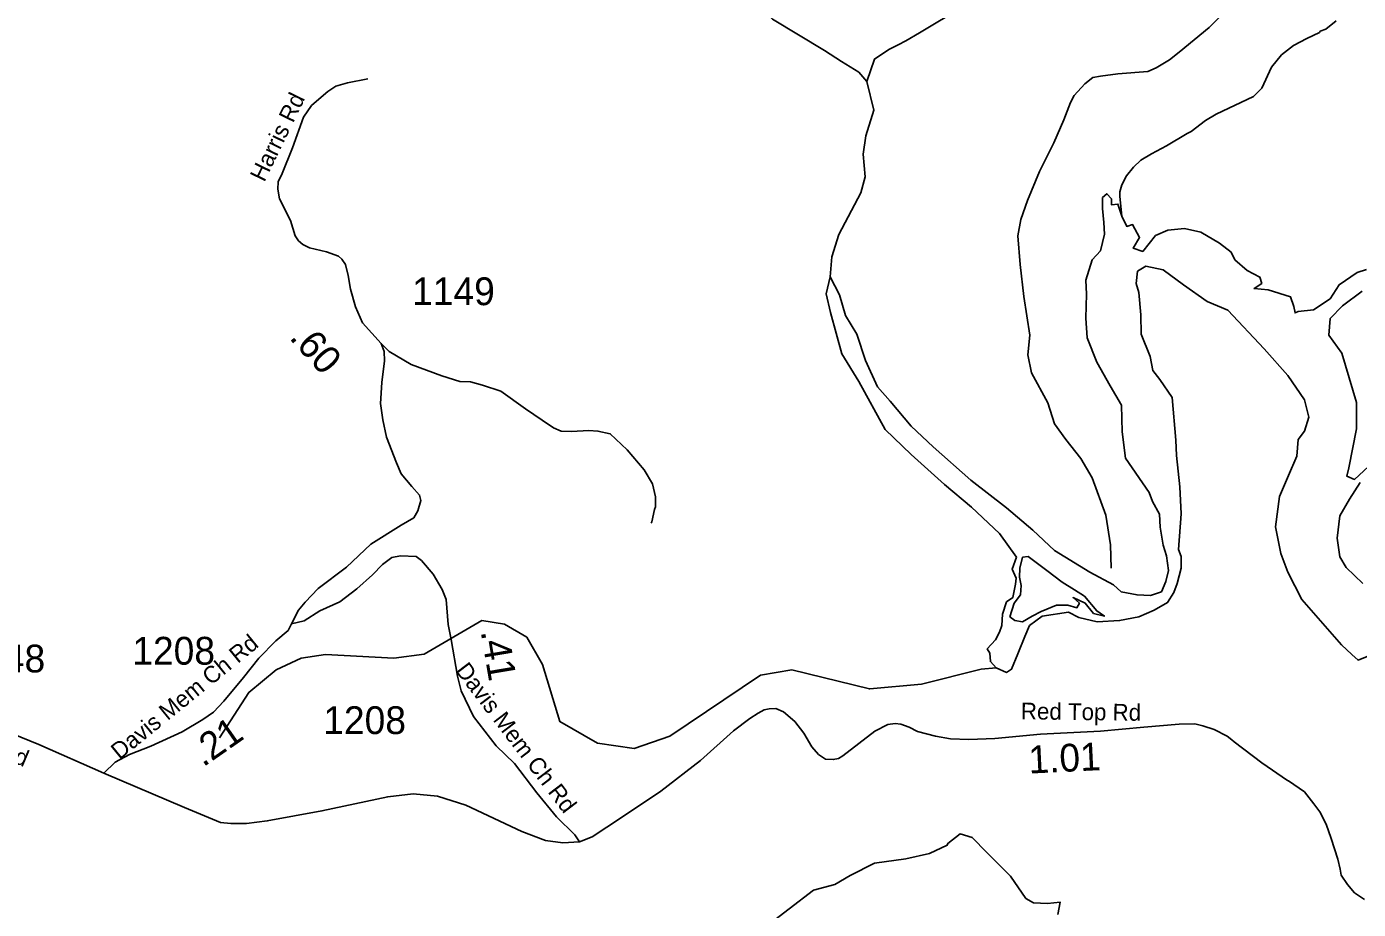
# Model space of a CAD drawing. Extents: x 1248224 to 1454986, y 825081 to 985870.
# Drawn here: x 1318874 to 1324862, y 870778 to 874747 of the extents above; entities that cross this region are included whole.
import ezdxf

# ---------------------------------------------------------------- set-up
doc = ezdxf.new("R2010")
doc.units = 0
for name, color, linetype in [('Exist Hydrographic Creek Single Shore', 7, 'Continuous'), ('Exist Hydrographic Island Shore', 7, 'Continuous'), ('Exist Hydrographic Misc Water Feature', 7, 'Continuous'), ('Exist Hydrographic Reservoir', 7, 'Continuous'), ('Exist Road Non-System Type 51', 7, 'Continuous'), ('Exist Road Secondary Mileage Hundredths English Label', 7, 'Continuous'), ('Exist Road Secondary Type 41 Attributed', 7, 'Continuous'), ('Exist Road Secondary Type 51 Attributed', 7, 'Continuous'), ('Exist Road Secondary Type 51 Label', 7, 'Continuous'), ('Exist Road Secondary Type 51 Number Label', 7, 'Continuous')]:
    doc.layers.add(name, color=color, linetype=linetype)

msp = doc.modelspace()

# ---------------------------------------------------------------- linework, layer by layer
at = {"layer": 'Exist Hydrographic Creek Single Shore'}
for points in [[(1320808.8, 876973.4), (1320929.1, 876789.6), (1321094.1, 876465.3), (1321322.1, 875990), (1321499.4, 875654.2), (1321600.7, 875464), (1321790.5, 875203.3), (1321980.7, 875014.1), (1322227.6, 874779.7), (1322461.9, 874640.2), (1322537.9, 874589.5), (1322616.2, 874542.5), (1322652.8, 874500.3), (1322683.7, 874370.7), (1322647.2, 874255.2), (1322635.9, 874173.6), (1322644.3, 874072.2), (1322624.6, 873998.9), (1322526.1, 873813), (1322495.2, 873711.7), (1322486.8, 873622.7)], [(1319741.5, 871549.2), (1319872.9, 871753.6), (1319996.9, 871855.9), (1320109.3, 871907), (1320217.3, 871924.5), (1320525.3, 871908.4), (1320661.1, 871926), (1320920.9, 872076.4)], [(1322666.1, 871769.6), (1322663.5, 871769.4), (1322315.6, 871855.1), (1322173.6, 871831.7), (1321766.5, 871557.6), (1321606.6, 871501.7), (1321440.6, 871524.8), (1321271.9, 871622.9), (1321193.1, 871878.5), (1321123, 872002.6), (1321022.3, 872061.1), (1320920.9, 872076.4)]]:
    msp.add_lwpolyline(points, dxfattribs=at)
at = {"layer": 'Exist Hydrographic Island Shore'}
msp.add_lwpolyline([(1323294.9, 872094), (1323315, 872154.5), (1323343.7, 872191.9), (1323346.6, 872235.1), (1323338, 872272.5), (1323340.9, 872312.8), (1323352.4, 872361.7), (1323378.3, 872364.6), (1323461.7, 872301.3), (1323530.7, 872249.4), (1323585.3, 872214.9), (1323631.4, 872186.1), (1323686, 872119.9), (1323720.5, 872096.9), (1323671.6, 872108.4), (1323634.2, 872154.5), (1323579.6, 872180.4), (1323608.4, 872154.5), (1323596.9, 872134.3), (1323556.6, 872145.8), (1323504.8, 872145.8), (1323435.8, 872117), (1323395.5, 872096.9), (1323352.4, 872071), (1323317.9, 872076.7), (1323294.9, 872094)], dxfattribs=at)
at = {"layer": 'Exist Hydrographic Misc Water Feature'}
for points in [[(1323036.2, 875103.7), (1323044.7, 875085.8), (1323047.5, 875045.7), (1323065.3, 874965.2), (1323091.7, 874908.5), (1323098.8, 874876.3), (1323087.6, 874836.6), (1322889.1, 874719.1), (1322828.1, 874682.7), (1322793.5, 874665.7), (1322750.7, 874644.6), (1322686.4, 874600.8), (1322652.8, 874500.3)], [(1324762.5, 874772.2), (1324715.5, 874735.5), (1324691.2, 874726.3), (1324687, 874720.4), (1324630.2, 874694), (1324571.4, 874661.7), (1324516.1, 874619.4), (1324472.5, 874564.6), (1324427.8, 874470), (1324390.8, 874433.1), (1324222.6, 874353.9), (1324175.7, 874325.3), (1324110.3, 874275.2), (1324092.4, 874267), (1324000.4, 874210.4)], [(1324000.4, 874210.4), (1323933, 874175), (1323884.6, 874145.8), (1323851.6, 874114.7), (1323820.6, 874075.7), (1323799.5, 874036.3), (1323790.5, 874004.5), (1323789.9, 873982.6), (1323799.6, 873894.2)], [(1323233.8, 871863.8), (1323166.6, 871857.8), (1322897.6, 871790.9), (1322666.1, 871769.6)]]:
    msp.add_lwpolyline(points, dxfattribs=at)
at = {"layer": 'Exist Hydrographic Reservoir'}
for points in [[(1323921.9, 872652.4), (1323815.4, 872806.5), (1323801, 872924.5), (1323798.1, 873045.4), (1323746.4, 873131.8), (1323686, 873238.3), (1323642.8, 873347.6), (1323637.1, 873436.9), (1323639.9, 873543.4), (1323637.1, 873606.7), (1323665.8, 873698.8), (1323703.2, 873739.1), (1323720.5, 873813.9), (1323717.6, 873865.7), (1323711.8, 873929), (1323711.8, 873978), (1323732, 873995.2), (1323752.1, 873972.2), (1323752.1, 873946.3), (1323780.9, 873949.2), (1323799.6, 873894.2), (1323821.1, 873848.5), (1323847, 873857.1), (1323878.7, 873799.5), (1323849.9, 873750.6), (1323893.1, 873736.2), (1323950.6, 873808.2), (1324005.2, 873831.2), (1324080, 873839.8), (1324154.8, 873822.5), (1324238.2, 873773.6), (1324290, 873733.3), (1324307.2, 873698.8), (1324361.9, 873649.9), (1324419.4, 873621.1), (1324428, 873592.3), (1324393.5, 873569.3), (1324456.8, 873563.5), (1324557.5, 873531.8), (1324571.8, 873488.7), (1324577.6, 873459.9), (1324592, 873465.6), (1324661, 873474.3), (1324735.8, 873523.2), (1324776, 873586.5), (1324856.6, 873641.2), (1324899.7, 873655.6)], [(1324059.2, 872677.2), (1324044.7, 872818.1), (1324041.9, 872887.2), (1324024.6, 873080), (1323970, 873160.6), (1323938.3, 873200.9), (1323926.8, 873264.2), (1323886.5, 873365), (1323883.7, 873451.3), (1323875, 873552.1), (1323863.5, 873592.4), (1323869.3, 873647), (1323906.7, 873670.1), (1323984.3, 873652.8), (1324076.4, 873586.6), (1324182.8, 873511.8), (1324274.8, 873471.5), (1324438.8, 873298.8), (1324545.2, 873177.9), (1324620, 873068.5), (1324640.1, 872990.8), (1324620, 872927.5), (1324591.2, 872890), (1324585.5, 872815.2), (1324548.1, 872728.9), (1324507.8, 872633.9), (1324490.5, 872498.6), (1324513.6, 872377.7), (1324545.2, 872294.2), (1324608.2, 872172), (1324786.5, 871967.6), (1324832.5, 871924.4), (1324861.3, 871898.5), (1324924.5, 871924.4)], [(1322486.8, 873622.7), (1322469.7, 873545.6), (1322489.4, 873461.1), (1322540, 873275.3), (1322616, 873151.3), (1322734.1, 872935.9), (1322852.3, 872823.3), (1323001.5, 872688.1), (1323122.5, 872586.7), (1323249.1, 872468.4), (1323325.1, 872361.4)], [(1323654.4, 872293.8), (1323496.8, 872392.4), (1323398.3, 872482.5), (1323280.1, 872583.9), (1323119.7, 872707.8), (1322950.8, 872857.1), (1322852.3, 872950), (1322756.6, 873062.7), (1322700.3, 873127.4), (1322646.9, 873245.7), (1322607.5, 873364), (1322556.8, 873448.5), (1322528.7, 873541.5), (1322486.8, 873622.7)], [(1324879.6, 873557.7), (1324790.4, 873491.5), (1324735.8, 873434), (1324730, 873359.1), (1324787.6, 873278.6), (1324853.7, 873056.9), (1324853.7, 872938.9), (1324819.2, 872763.3), (1324810.6, 872725.9), (1324845.1, 872711.5), (1324908.4, 872769.1)], [(1324871, 872697.1), (1324822.1, 872622.3), (1324778.9, 872547.5), (1324767.4, 872446.7), (1324778.9, 872363.3), (1324807.6, 872315.5), (1324882.4, 872243.5)], [(1323325.1, 872361.4), (1323305.7, 872307.1), (1323323, 872266.8), (1323320.1, 872240.9), (1323308.6, 872180.4), (1323279.9, 872160.3), (1323262.6, 872105.6), (1323259.7, 872053.8), (1323248.2, 872025), (1323231, 871990.5), (1323193.6, 871950.2), (1323205.1, 871930), (1323207.9, 871892.6), (1323233.8, 871863.8), (1323279.9, 871843.7), (1323302.9, 871858.1), (1323331.6, 871927.1), (1323363.3, 872004.8), (1323383.4, 872053.8), (1323440.9, 872096.9), (1323558.8, 872114.2), (1323604.9, 872091.2), (1323688.3, 872071), (1323788.9, 872076.8), (1323875.2, 872094.1), (1323944.3, 872122.9), (1324004.7, 872157.4), (1324033.4, 872203.4), (1324047.8, 872243.7), (1324065.1, 872312.8), (1324065.1, 872364.6), (1324053.6, 872396.3), (1324065, 872556.3), (1324059.2, 872677.2)], [(1323654.4, 872293.8), (1323760.8, 872237.9), (1323795.3, 872206.3), (1323867.2, 872191.9), (1323927.6, 872189), (1323976.5, 872206.3), (1323996.6, 872252.3), (1324008.2, 872301.3), (1323999.5, 872367.5), (1323985.1, 872416.4), (1323970.8, 872497), (1323967.9, 872554.5), (1323936.2, 872612.1), (1323921.9, 872652.4)], [(1323366.8, 870827.7), (1323298.6, 870928.2), (1323192.2, 871034.7), (1323126, 871100.9), (1323071.4, 871118.2), (1323016.7, 871075), (1323013.8, 871066.4), (1322933.3, 871029), (1322826.9, 871005.9), (1322686, 870985.8), (1322576.7, 870931.1), (1322507.6, 870890.8), (1322412.7, 870864.9), (1322303.4, 870781.4), (1322153.9, 870666.3)], [(1323510.6, 870755.7), (1323522.2, 870810.4), (1323464.6, 870804.6), (1323401.3, 870807.5), (1323366.8, 870827.7)]]:
    msp.add_lwpolyline(points, dxfattribs=at)
at = {"layer": 'Exist Road Non-System Type 51'}
for points in [[(1324013.5, 874596.9), (1323953.5, 874561.8), (1323915.8, 874545.6), (1323781, 874534.8), (1323702.9, 874524), (1323667.9, 874518.6), (1323632.8, 874489), (1323584.3, 874437.7), (1323568.1, 874405.4), (1323538.5, 874327.2), (1323492.7, 874224.7), (1323428, 874095.2), (1323374.1, 873965.8), (1323344.5, 873879.5), (1323331, 873806.7), (1323341.8, 873677.2), (1323357.9, 873534.3), (1323384.9, 873360.3), (1323376.9, 873271.3), (1323393, 873190.4), (1323465.8, 873055.6), (1323495.4, 872961.2), (1323546.6, 872891.1), (1323614, 872804.8), (1323665.2, 872718.5), (1323727, 872549.9), (1323748.5, 872417.8), (1323751.2, 872312.6)], [(1320468.2, 873322.3), (1320503.6, 873285.7), (1320603.1, 873227.4), (1320741.4, 873176.4), (1320821.5, 873152.1), (1320870.1, 873149.7), (1320923.5, 873135.1), (1321006, 873108.4), (1321117.6, 873028.3), (1321192.9, 872977.2), (1321243.8, 872943.2), (1321277.8, 872928.7), (1321323.9, 872926.2), (1321401.6, 872931.1), (1321442.8, 872928.7), (1321498.7, 872916.5), (1321573.9, 872843.7), (1321651.6, 872753.8), (1321688, 872690.7), (1321702.5, 872632.4), (1321702.5, 872588.6), (1321697.7, 872576.5), (1321685.5, 872520.6), (1321682.7, 872514.3)]]:
    msp.add_lwpolyline(points, dxfattribs=at)
at = {"layer": 'Exist Road Secondary Type 41 Attributed'}
for points in [[(1320065.3, 872061.3), (1320096.8, 872124.2), (1320126.4, 872159.3), (1320185.5, 872220.4), (1320313.1, 872316.7), (1320422.3, 872420.6), (1320557.7, 872505.9), (1320614.7, 872538.9), (1320632.8, 872569.7), (1320646.8, 872617.2), (1320641.2, 872641), (1320606.3, 872678.7), (1320558.8, 872736), (1320537.8, 872786.4), (1320491.7, 872901), (1320475.2, 872979.8), (1320465.4, 873052.5), (1320471, 873147.6), (1320483.6, 873244.1), (1320482.2, 873286), (1320468.2, 873322.3), (1320426.4, 873368.8), (1320384.5, 873414.9), (1320352.3, 873487.6), (1320330, 873567.3), (1320320.2, 873627.4), (1320307.6, 873677.8), (1320290.9, 873701.5), (1320276.9, 873715.5), (1320222.4, 873733.7), (1320145.6, 873751.9), (1320116.3, 873767.2), (1320096.7, 873784), (1320081.4, 873806.4), (1320060.4, 873874.9), (1320010.4, 873973.3), (1320003.4, 874016.7), (1320004.8, 874048.8), (1320023, 874086.6), (1320069.1, 874201.2), (1320119.4, 874339.6), (1320155.6, 874392), (1320187.7, 874421.3), (1320228.3, 874454.9), (1320264.6, 874478.7), (1320316.3, 874494), (1320408.1, 874512.1)], [(1320065.3, 872061.3), (1320121.4, 872076.1), (1320191.9, 872120.2), (1320283.1, 872161.4), (1320359.5, 872218.8), (1320428.6, 872282.1), (1320474.2, 872329.1), (1320516.8, 872360), (1320555.1, 872367.4), (1320625.6, 872364.5), (1320649.2, 872346.8), (1320702.1, 872285), (1320743.2, 872215.9), (1320760.9, 872171.7), (1320769.7, 872058.4), (1320782.9, 871992.2)], [(1320782.9, 871992.2), (1320810.9, 871827.4), (1320828.5, 871761.2), (1320884.2, 871645.9), (1320985.7, 871513.4), (1321068, 871434), (1321168, 871301.6), (1321257.3, 871194.8), (1321339.6, 871113.9), (1321360.2, 871081.5)]]:
    msp.add_lwpolyline(points, dxfattribs=at)
at = {"layer": 'Exist Road Secondary Type 51 Attributed'}
for points in [[(1324243.7, 874795.2), (1324191.1, 874742.5), (1324056.1, 874632), (1324013.5, 874596.9)], [(1319221.9, 871390), (1319272.6, 871440), (1319337.3, 871475.3), (1319432.8, 871512.1), (1319574, 871576.8), (1319666.6, 871631.3), (1319715.1, 871665.1), (1319760.7, 871715.1), (1319848.9, 871821.1), (1319918, 871907.9), (1319994.4, 871985.8), (1320049.9, 872032.3), (1320065.3, 872061.3)], [(1318052.7, 871939.5), (1318326.1, 871792.7), (1318611.3, 871648.5), (1318928.9, 871519), (1319221.9, 871390)], [(1321360.2, 871081.5), (1321417.8, 871104), (1321549.3, 871191.1), (1321725.5, 871309.4), (1321903.9, 871447.8), (1322053.4, 871581.7), (1322125.4, 871635.7), (1322163.3, 871660.3), (1322191.2, 871674.8), (1322213.5, 871680.4), (1322243.6, 871681.5), (1322278.2, 871665.9), (1322328.3, 871622.4), (1322368.5, 871569.9), (1322405.3, 871508.5), (1322435.4, 871475), (1322466.6, 871453.8), (1322501.2, 871451.6), (1322524.6, 871456.1), (1322543.6, 871468.3), (1322688.5, 871578.8), (1322746.1, 871610.1), (1322779.5, 871614.6), (1322805.2, 871611.2), (1322842, 871597.8), (1322879.9, 871577.7), (1322961.3, 871557.6), (1323028.2, 871545.4), (1323110.4, 871542.2), (1323227.5, 871546.7), (1323433.7, 871565.7), (1323702.8, 871578.8), (1323897.9, 871597.8), (1324056.3, 871611.2), (1324126.5, 871612.3), (1324163.3, 871603.4), (1324213.5, 871586.6), (1324272.6, 871557.6), (1324293.3, 871540.6), (1324303.5, 871532.2), (1324428.4, 871437.4), (1324544.3, 871358.1), (1324547.7, 871355.9), (1324620.2, 871306.8), (1324662.5, 871253.2), (1324689.3, 871217.5), (1324718.3, 871161.7), (1324740.6, 871097), (1324769.5, 871004.2), (1324780.7, 870959.5), (1324785.1, 870932.8), (1324814.1, 870890.3), (1324845.4, 870852.4), (1324890, 870823.4)], [(1319221.9, 871390), (1319584.6, 871236.3), (1319745.2, 871168.5), (1319791.7, 871164.7), (1319863.2, 871164.7), (1319956.1, 871176.3), (1320201.9, 871220.8), (1320497.9, 871284.7), (1320612.1, 871298.3), (1320722.3, 871286.7), (1320849.2, 871246.2), (1321100.7, 871128), (1321207.2, 871087.4), (1321284.6, 871077.7), (1321360.2, 871081.5)]]:
    msp.add_lwpolyline(points, dxfattribs=at)

# ---------------------------------------------------------------- texts
at = {"layer": 'Exist Road Secondary Mileage Hundredths English Label'}
for s, rotation, p in [('.60', 312.00363, (1320051.7, 873346.3)), ('.41', 279.62064, (1320915.4, 872027.9)), ('.21', 34.8966, (1319667.8, 871415.8)), ('1.01', 2.79486, (1323381.8, 871388.7))]:
    msp.add_text(s, height=125, rotation=rotation, dxfattribs=at).set_placement(p)
at = {"layer": 'Exist Road Secondary Type 51 Label'}
for s, rotation, p in [('Harris Rd', 64.0558, (1319942.6, 874044.7)), ('Davis Mem Ch Rd', 39.15791, (1319291.9, 871448.4)), ('Davis Mem Ch Rd', 307.27914, (1320799.5, 871851.7)), ('Red Top Rd', 336.93288, (1318365.6, 871628.9)), ('Red Top Rd', 359.26694, (1323344.4, 871632.9))]:
    msp.add_text(s, height=75, rotation=rotation, dxfattribs=at).set_placement(p)
at = {"layer": 'Exist Road Secondary Type 51 Number Label'}
for s, p in [('1149', (1320607.6, 873494.7)), ('1208', (1319349.3, 871878.4)), ('1148', (1318585.7, 871843.5)), ('1208', (1320208, 871566.4))]:
    msp.add_text(s, height=125, dxfattribs=at).set_placement(p)

doc.saveas('drawing.dxf')
